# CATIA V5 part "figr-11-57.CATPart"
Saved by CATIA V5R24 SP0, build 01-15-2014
Part number: Part1
Bounding box of the stored display mesh (mm): x -55 to 55, y -105 to 155, z -20 to 14.953
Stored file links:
  D:\KAVITA\CATIA V5-6R2014 Project_ Kavita\CATIA V5-6R2014_partfiles\Partfiles\c11_catia_v5-6r2014_prt\figr-11-57.CATPart
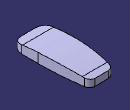
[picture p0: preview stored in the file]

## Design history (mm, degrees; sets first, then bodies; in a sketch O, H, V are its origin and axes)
Set1
  Extrude1: Element1 Sketch2, Lim1 50, Lim2 50, Direction yz-plane
  Sketch1 on xy-plane, origin (0, 0, 0), H (1, 0, 0), V (0, 1, 0)
    arc A1 centre (25, -75) radius 25 from (25, -100) to (50, -75) ccw
    line L1 (50, -75) -> (50, -15)
    point P4 (50, -15)
    arc A2 centre (-950, -15) radius 1000 from (50, -15) to (38.3367, 137.2843) ccw
    line L2 (23.5117, 150) -> (-23.5117, 150)
    line L3 (25, -100) -> (-25, -100)
    arc A3 centre (-25, -75) radius 25 from (-25, -100) to (-50, -75) cw
    line L4 (-50, -75) -> (-50, -15)
    point P9 (-50, -15)
    arc A4 centre (950, -15) radius 1000 from (-50, -15) to (-38.3367, 137.2843) cw
    reference projected line E1 (-50, -100) -> (50, -100) from edge of Extrude1
    axis line L5 (0, 170.4214) -> (0, -120.6595)
    point P11 (0, 170.4214)
    reference projected line E2 (50, -70) -> (50, 129.9971) from edge of Extrude1
    reference projected line E3 (-50, 129.9971) -> (-50, -70) from edge of Extrude1
    reference projected line E4 (-50, -100) -> (50, -100) from edge of Extrude1
    reference projected line E5 (50, 150) -> (-50, 150) from edge of Extrude1
    arc A5 centre (-23.5117, 135) radius 15 from (-38.3367, 137.2843) to (-23.5117, 150) cw
    arc A6 centre (23.5117, 135) radius 15 from (38.3367, 137.2843) to (23.5117, 150) ccw
    distance E4 P4 = 85
    radius A2 = 1000
    radius A5 = 15
    radius A6 = 15
    radius A1 = 25
    radius A3 = 25
    radius A4 = 1000
    tangency: L1 A1, A2 L1, L3 A1, A3 L3, A4 L4, L5 A3, A5 L2, A5 A4, A6 A2, A6 L2, A3 L4
    horizontal: L2 H
    coincidence: L3 E1, P11 V, L1 E2, L4 E3, L2 E5
    symmetry: P4 P9 L5
  Extrude2: Element1 Sketch1, Lim1 50, Lim2 20, Direction xy-plane
  Split1: ToCut Extrude2, Cutting Extrude1
  Split2: ToCut Extrude1, Cutting Split1
  Join1: Elements (Split2; Split1)
Body1 (main body)
  Sketch2 on yz-plane, origin (0, 0, 0), H (0, 1, 0), V (0, 0, 1)
    point P1 (-100, 0)
    line L1 (-100, 0) -> (-70, 3.8724)
    point P2 (-70, 3.8724)
    arc A1 centre (26.0141, -739.9564) radius 750 from (-70, 3.8724) to (129.9971, 2.8003) cw
    point P4 (129.9971, 2.8003)
    line L2 (129.9971, 2.8003) -> (150, 0)
    point P5 (150, 0)
    distance P1 P5 = 250
    distance P1 O = 100
    radius A1 = 750
    distance P2 P4 = 200
    distance P2 V = 70
    coincidence: P1 H, P5 H
    tangency: A1 L1, L2 A1
  ThickSurface1: BotOffset 0, Surface Join1, TopOffset 5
